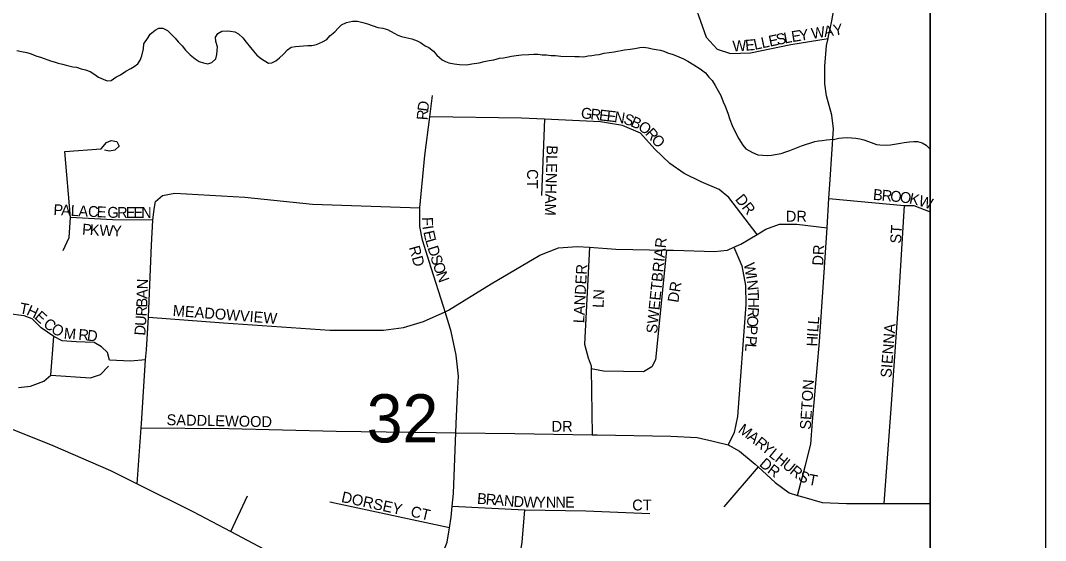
# Model space of a CAD drawing. Extents: x -209 to 4852, y 0 to 905.
# Drawn here: x 555.98 to 573.77, y 228.69 to 237.73 of the extents above; entities that cross this region are included whole.
import ezdxf

# ---------------------------------------------------------------- set-up
doc = ezdxf.new("R2010")
doc.units = 0
for name, color, linetype in [('Default', 7, 'Continuous'), ('GM_X_County_Road', 7, 'Continuous'), ('GM_X_County_Road_Text', 7, 'Continuous'), ('GM_X_Interstate_Location', 7, 'Continuous'), ('GM_X_Minor_Lake_Text', 7, 'Continuous'), ('GM_X_Minor_River', 7, 'Continuous'), ('GM_X_Township_Road_Text', 7, 'Continuous'), ('GM_X_Township_Text', 7, 'Continuous'), ('SH_Data', 7, 'Continuous')]:
    doc.layers.add(name, color=color, linetype=linetype)

msp = doc.modelspace()

# ---------------------------------------------------------------- linework, layer by layer
at = {"layer": 'Default'}
msp.add_lwpolyline([(571.768, 202.559), (571.768, 338.559), (435.768, 338.559), (435.768, 202.559)], close=True, dxfattribs=at)
at = {"layer": 'GM_X_County_Road'}
for points in [[(557.712, 236.78), (557.805, 236.846), (557.89, 236.89), (557.951, 236.926), (558.013, 236.971), (558.053, 237.038), (558.085, 237.113), (558.111, 237.234), (558.121, 237.318), (558.192, 237.43), (558.231, 237.49), (558.317, 237.556), (558.378, 237.592), (558.447, 237.591), (558.53, 237.551), (558.589, 237.496), (558.663, 237.418), (558.715, 237.356), (558.782, 237.286), (558.841, 237.208), (558.922, 237.13), (559.012, 237.06), (559.079, 237.012), (559.155, 236.988), (559.23, 236.971), (559.299, 236.999), (559.369, 237.058), (559.386, 237.134), (559.397, 237.271), (559.369, 237.362), (559.363, 237.439), (559.403, 237.499), (559.472, 237.542), (559.564, 237.548), (559.625, 237.539), (559.7, 237.529), (559.76, 237.497), (559.835, 237.427), (559.894, 237.349), (559.967, 237.256), (560.019, 237.194), (560.078, 237.124), (560.16, 237.061), (560.28, 236.982), (560.341, 236.989), (560.41, 237.025), (560.473, 237.077), (560.543, 237.143), (560.613, 237.217), (560.675, 237.262), (560.751, 237.275), (560.82, 237.281), (560.889, 237.287), (560.965, 237.292), (561.033, 237.291), (561.117, 237.311), (561.217, 237.354), (561.294, 237.398), (561.349, 237.458), (561.435, 237.532), (561.489, 237.591), (561.552, 237.65), (561.636, 237.694), (561.743, 237.714), (561.827, 237.712), (561.918, 237.694), (562.001, 237.669), (562.182, 237.604), (562.265, 237.594), (562.348, 237.57), (562.461, 237.506), (562.528, 237.474), (562.589, 237.45), (562.664, 237.432), (562.77, 237.407), (562.861, 237.374), (562.921, 237.342), (563.003, 237.287), (563.063, 237.255), (563.145, 237.192), (563.204, 237.122), (563.294, 237.044), (563.354, 237.012), (563.414, 236.988), (563.505, 236.971), (563.596, 236.961), (563.725, 236.957), (563.809, 236.971), (563.939, 236.99), (564.023, 237.011), (564.115, 237.031), (564.191, 237.045), (564.291, 237.073), (564.359, 237.079), (564.421, 237.092), (564.497, 237.106), (564.581, 237.119), (564.673, 237.132), (564.802, 237.136), (564.886, 237.141), (564.962, 237.14)], [(555.912, 237.205), (555.995, 237.188), (556.086, 237.171), (556.162, 237.146), (556.244, 237.113), (556.343, 237.081), (556.501, 237.023), (556.561, 237.007), (556.629, 236.982), (556.705, 236.965), (556.773, 236.948), (556.886, 236.923), (556.947, 236.913), (557.03, 236.889), (557.106, 236.871), (557.188, 236.839), (557.248, 236.799), (557.331, 236.744), (557.413, 236.704), (557.481, 236.68), (557.55, 236.685), (557.635, 236.744), (557.712, 236.78)], [(564.962, 237.14), (565.03, 237.13), (565.106, 237.128), (565.19, 237.119), (565.266, 237.117), (565.357, 237.107), (565.6, 237.101), (565.676, 237.099), (565.752, 237.097), (565.828, 237.11), (565.897, 237.116), (565.958, 237.13), (566.019, 237.136), (566.111, 237.157), (566.279, 237.183), (566.462, 237.216), (566.561, 237.229), (566.638, 237.242), (566.729, 237.255), (566.79, 237.261), (566.874, 237.252), (566.942, 237.235), (567.01, 237.225), (567.086, 237.208), (567.146, 237.192), (567.206, 237.167), (567.304, 237.134), (567.402, 237.094), (567.485, 237.062), (567.56, 237.022), (567.665, 236.958), (567.777, 236.887), (567.867, 236.816), (567.926, 236.739), (567.985, 236.684), (568.037, 236.599), (568.088, 236.507), (568.131, 236.422), (568.174, 236.314), (568.21, 236.238), (568.253, 236.115), (568.288, 236.007), (568.331, 235.9), (568.403, 235.746), (568.447, 235.669), (568.513, 235.561), (568.565, 235.499), (568.685, 235.435), (568.775, 235.395), (568.935, 235.383), (569.011, 235.389), (569.11, 235.402), (569.179, 235.415), (569.263, 235.443), (569.332, 235.465), (569.532, 235.551), (569.762, 235.621), (569.831, 235.635), (569.892, 235.641), (569.968, 235.654), (570.029, 235.66), (570.113, 235.666), (570.182, 235.679), (570.243, 235.685), (570.326, 235.691), (570.402, 235.689), (570.478, 235.679), (570.547, 235.67), (570.615, 235.653), (570.697, 235.621), (570.833, 235.572), (570.894, 235.563), (571.015, 235.56), (571.076, 235.566), (571.145, 235.579), (571.252, 235.592), (571.313, 235.605), (571.405, 235.618), (571.481, 235.624), (571.549, 235.622), (571.625, 235.598), (571.7, 235.558), (571.768, 235.492)]]:
    msp.add_lwpolyline(points, dxfattribs=at)
at = {"layer": 'GM_X_County_Road_Text'}
msp.add_lwpolyline([(554.875, 231.005), (556.54, 230.339), (557.539, 229.91), (558.003, 229.678), (558.966, 229.196), (559.628, 228.845), (560.489, 228.388), (562.093, 227.608), (562.726, 227.285), (563.943, 226.661), (565.196, 226.052), (565.675, 225.818), (566.474, 225.41), (567.714, 224.775), (569.815, 223.725), (570.343, 223.445), (571.432, 222.869), (571.65, 222.76), (571.768, 222.7)], dxfattribs=at)
at = {"layer": 'GM_X_Minor_Lake_Text'}
msp.add_lwpolyline([(529.706, 202.559), (571.768, 202.559), (571.768, 262.071), (562.454, 262.602), (559.929, 262.758), (554.405, 263.075), (535.693, 268.436), (531.778, 225.399), (531.472, 222.006), (531.173, 218.724), (530.557, 211.945), (530.109, 207.025), (529.915, 204.912), (529.85, 204.169)], close=True, dxfattribs=at)
at = {"layer": 'GM_X_Minor_River'}
msp.add_lwpolyline([(571.768, 220.234), (571.768, 241.24), (553.028, 241.998), (551.202, 220.877)], close=True, dxfattribs=at)
at = {"layer": 'GM_X_Township_Text'}
for points in [[(570.002, 237.453), (570.03, 237.583), (570.059, 237.718), (570.18, 238.414), (570.301, 238.989), (570.301, 239.32), (570.291, 239.477), (570.271, 239.836), (570.18, 240.472), (570.018, 241.325)], [(567.682, 237.993), (567.876, 237.438), (568.069, 237.231), (568.301, 237.154), (568.65, 237.167), (569.347, 237.309), (569.994, 237.414)], [(569.463, 229.475), (569.605, 230.002), (569.696, 230.365), (569.726, 230.758), (569.847, 232.15), (569.976, 234.123), (570.008, 234.635), (570.029, 234.964), (570.09, 235.842), (570.059, 236.084), (569.968, 236.417), (569.938, 236.628), (569.938, 236.931), (569.968, 237.294), (569.994, 237.414), (570.002, 237.453)], [(558.003, 229.678), (558.07, 230.646), (558.076, 230.722), (558.15, 231.829), (558.162, 232.001), (558.197, 232.57), (558.206, 232.716), (558.249, 233.821), (558.276, 234.259), (558.299, 234.448), (558.321, 234.579), (558.44, 234.683), (558.654, 234.724), (559.874, 234.656), (561.045, 234.536), (562.909, 234.471), (562.996, 235.381), (563.08, 236.055), (563.126, 236.421)], [(568.761, 234.01), (568.27, 234.653), (568.104, 234.788), (567.794, 234.922), (567.494, 235.067), (567.246, 235.243), (566.988, 235.491), (566.74, 235.77), (566.429, 235.904), (566.047, 235.966), (565.07, 236.011), (564.671, 236.029), (563.08, 236.055)], [(565.07, 236.011), (565.023, 234.684)], [(556.718, 233.727), (556.823, 233.955), (556.846, 234.301), (556.745, 235.448), (557.379, 235.499), (557.47, 235.608), (557.552, 235.64), (557.652, 235.626), (557.688, 235.54), (557.615, 235.476), (557.524, 235.453), (557.433, 235.476)], [(570.008, 234.635), (571.315, 234.51), (571.482, 234.51), (571.768, 234.399)], [(571.315, 234.51), (571.209, 232.801), (571.088, 231.061), (570.963, 229.336)], [(563.565, 231.236), (563.581, 231.545), (563.538, 231.913), (563.451, 232.325), (563.349, 232.667), (563.321, 232.758), (563.104, 233.43), (562.953, 233.907), (562.909, 234.146), (562.909, 234.471)], [(558.276, 234.259), (557.574, 234.264), (556.846, 234.301)], [(568.251, 233.738), (568.361, 233.787), (568.48, 233.842), (568.761, 234.01), (568.914, 234.102), (569.152, 234.188), (569.455, 234.188), (569.976, 234.123)], [(558.197, 232.57), (559.499, 232.475), (561.349, 232.347), (562.281, 232.347), (562.628, 232.39), (562.974, 232.498), (563.349, 232.667), (563.408, 232.693), (564.145, 233.148), (564.99, 233.647), (565.315, 233.777), (565.641, 233.799), (565.852, 233.785), (566.313, 233.755), (567.19, 233.736), (567.31, 233.733), (568.025, 233.712), (568.242, 233.733), (568.251, 233.738)], [(565.852, 233.785), (565.768, 232.1), (565.829, 231.862), (565.881, 231.727), (565.882, 231.673), (565.898, 230.527)], [(568.361, 233.787), (568.497, 233.464), (568.559, 233.123), (568.57, 232.792), (568.425, 230.848), (568.363, 230.569), (568.263, 230.352)], [(567.19, 233.736), (566.998, 231.831), (566.936, 231.707), (566.791, 231.624), (566.098, 231.635), (565.882, 231.673)], [(558.15, 231.829), (557.886, 231.807), (557.52, 231.823), (557.488, 231.96), (557.383, 232.056), (557.259, 232.131), (556.943, 232.142), (556.702, 232.159), (556.557, 232.235), (556.336, 232.386), (556.179, 232.54), (556.042, 232.593), (555.77, 232.627)], [(556.506, 231.566), (556.557, 232.235)], [(555.941, 231.35), (556.154, 231.373), (556.38, 231.459), (556.506, 231.566), (557.195, 231.518), (557.368, 231.578), (557.506, 231.719)], [(562.726, 227.285), (562.996, 227.86), (563.278, 228.402), (563.386, 228.663), (563.424, 228.912), (563.451, 229.096), (563.472, 229.288), (563.495, 229.508), (563.517, 230.115), (563.533, 230.564), (563.538, 230.721), (563.565, 231.231), (563.565, 231.236)], [(558.07, 230.646), (559.593, 230.635), (561.457, 230.592), (563.191, 230.57), (563.533, 230.564), (564.557, 230.548), (565.898, 230.527), (565.987, 230.526), (567.266, 230.504), (567.721, 230.482), (568.003, 230.418), (568.263, 230.352)], [(568.263, 230.352), (568.455, 230.244), (568.727, 230.017), (568.779, 229.97), (569.075, 229.699), (569.318, 229.518), (569.463, 229.475), (569.575, 229.442), (569.893, 229.351), (570.316, 229.336), (570.963, 229.336), (571.768, 229.336)], [(568.779, 229.97), (568.183, 229.276)], [(559.628, 228.845), (559.918, 229.465)], [(563.424, 228.912), (561.349, 229.356)], [(563.472, 229.288), (564.73, 229.226), (565.792, 229.204), (566.898, 229.161)], [(563.943, 226.661), (564.275, 227.297), (564.513, 227.904), (564.622, 228.272), (564.687, 228.662), (564.73, 229.226)]]:
    msp.add_lwpolyline(points, dxfattribs=at)
at = {"layer": 'SH_Data'}
for p, q in [((573.768, 340.559), (573.768, 200.559)), ((571.768, 338.559), (571.768, 202.559))]:
    msp.add_line(p, q, dxfattribs=at)

# ---------------------------------------------------------------- texts
at = {"layer": 'GM_X_Interstate_Location'}
for s, height, rotation, p in [('S', 0.189, 12.0622, (569.114, 237.298)), ('L', 0.189, 10.9402, (569.243, 237.325)), ('E', 0.189, 9.1928, (569.373, 237.35)), ('Y', 0.189, 8.8226, (569.504, 237.371)), ('W', 0.189, 8.8234, (569.718, 237.405)), ('A', 0.189, 8.8226, (569.933, 237.438)), ('Y', 0.189, 8.8226, (570.097, 237.463)), ('W', 0.189, 2.9774, (568.341, 237.188)), ('E', 0.189, 4.5939, (568.563, 237.2)), ('L', 0.189, 11.9986, (568.723, 237.214)), ('L', 0.189, 12.0622, (568.853, 237.242)), ('E', 0.189, 12.0547, (568.984, 237.27)), ('D', 0.189, 82.7231, (563.053, 236.137)), ('R', 0.189, 85.7223, (563.042, 235.99)), ('G', 0.189, 353.4064, (565.697, 236.03)), ('R', 0.189, 353.3809, (565.862, 236.01)), ('E', 0.189, 353.4219, (566.012, 235.993)), ('E', 0.189, 353.4003, (566.144, 235.978)), ('N', 0.189, 351.1774, (566.275, 235.963)), ('S', 0.189, 340.4766, (566.43, 235.94)), ('B', 0.189, 336.7281, (566.553, 235.896)), ('O', 0.189, 325.2247, (566.682, 235.842)), ('R', 0.189, 312.2002, (566.81, 235.754)), ('O', 0.189, 312.8974, (566.913, 235.641)), ('BLENHAM', 0.1894, 268.3406, (565.113, 235.56)), ('CT', 0.1894, 270, (564.771, 235.144)), ('DR', 0.1894, 308.6634, (568.372, 234.616)), ('B', 0.189, 354.6883, (570.768, 234.612)), ('R', 0.189, 354.6883, (570.918, 234.599)), ('O', 0.189, 354.6883, (571.067, 234.585)), ('O', 0.189, 352.3472, (571.231, 234.57)), ('K', 0.189, 347.6649, (571.392, 234.548)), ('W', 0.189, 342.9827, (571.551, 234.513)), ('P', 0.189, 357.2399, (556.546, 234.346)), ('A', 0.189, 357.2446, (556.679, 234.34)), ('L', 0.189, 357.2399, (556.846, 234.332)), ('A', 0.189, 357.2446, (556.979, 234.325)), ('C', 0.189, 357.2482, (557.146, 234.317)), ('E', 0.189, 357.2399, (557.295, 234.31)), ('G', 0.189, 358.394, (557.483, 234.301)), ('R', 0.189, 359.9466, (557.655, 234.296)), ('E', 0.189, 359.9956, (557.805, 234.296)), ('E', 0.189, 359.9956, (557.938, 234.296)), ('N', 0.189, 359.9929, (558.072, 234.296)), ('DR', 0.1894, 0, (569.261, 234.23)), ('P', 0.189, 356.2822, (557.043, 234.008)), ('K', 0.189, 356.4071, (557.176, 233.999)), ('W', 0.189, 357.0462, (557.345, 233.989)), ('Y', 0.189, 358.9102, (557.568, 233.977)), ('F', 0.189, 271.5031, (562.947, 234.309)), ('I', 0.189, 278.9586, (562.953, 234.149)), ('ST', 0.1894, 86.4254, (571.259, 233.846)), ('E', 0.189, 282.5544, (562.968, 234.054)), ('RD', 0.1894, 285.526, (562.718, 233.784)), ('L', 0.189, 286.4934, (563.001, 233.91)), ('D', 0.189, 287.1881, (563.039, 233.78)), ('SWEETBRIAR', 0.1894, 84.224, (567.026, 232.281)), ('DR', 0.1894, 86.9884, (569.909, 233.463)), ('S', 0.189, 287.3772, (563.089, 233.62)), ('O', 0.189, 289.2108, (563.131, 233.487)), ('LANDER', 0.1894, 86.9313, (565.76, 232.463)), ('W', 0.189, 280.1755, (568.53, 233.5)), ('N', 0.189, 290.2016, (563.187, 233.326)), ('I', 0.189, 280.1858, (568.568, 233.287)), ('N', 0.189, 88.2074, (558.186, 233.054)), ('DR', 0.1894, 81.0327, (567.394, 232.816)), ('N', 0.189, 276.3957, (568.582, 233.208)), ('B', 0.189, 87.9147, (558.176, 232.736)), ('A', 0.189, 88.2251, (558.181, 232.887)), ('LN', 0.1894, 86.9775, (566.097, 232.729)), ('T', 0.189, 272.9252, (568.6, 233.046)), ('H', 0.189, 270.5246, (568.607, 232.915)), ('T', 0.189, 349.1454, (555.949, 232.641)), ('H', 0.189, 335.4095, (556.068, 232.62)), ('R', 0.189, 86.4633, (558.166, 232.581)), ('MEADOWVIEW', 0.1894, 355.4707, (558.615, 232.596)), ('R', 0.189, 266.2812, (568.609, 232.752)), ('E', 0.189, 317.7061, (556.207, 232.559)), ('C', 0.189, 322.9625, (556.358, 232.421)), ('U', 0.189, 85.9315, (558.154, 232.413)), ('O', 0.189, 265.6901, (568.599, 232.603)), ('L', 0.189, 85.3498, (569.833, 232.439)), ('O', 0.189, 327.5966, (556.492, 232.321)), ('M', 0.189, 354.7134, (556.724, 232.201)), ('R', 0.189, 355.7466, (556.977, 232.178)), ('D', 0.189, 352.791, (557.124, 232.167)), ('D', 0.189, 85.9533, (558.142, 232.247)), ('P', 0.189, 265.6788, (568.587, 232.437)), ('L', 0.189, 85.377, (569.822, 232.306)), ('SIENNA', 0.1894, 85.5135, (571.092, 231.513)), ('P', 0.189, 265.6853, (568.573, 232.254)), ('H', 0.189, 87.5513, (569.809, 232.059)), ('I', 0.189, 85.7991, (569.816, 232.224)), ('L', 0.189, 265.6958, (568.563, 232.121)), ('SETON', 0.1894, 86.183, (569.692, 230.613)), ('SADDLEWOOD', 0.1894, 358.8315, (558.512, 230.696)), ('DR', 0.1894, 0, (565.195, 230.58)), ('M', 0.189, 323.4798, (568.419, 230.583)), ('A', 0.189, 322.0503, (568.578, 230.465)), ('R', 0.189, 320.7978, (568.709, 230.363)), ('Y', 0.189, 320.7906, (568.825, 230.268)), ('L', 0.189, 320.7874, (568.954, 230.163)), ('H', 0.189, 320.7906, (569.058, 230.079)), ('D', 0.189, 319.0218, (568.788, 230)), ('U', 0.189, 320.7833, (569.187, 229.973)), ('R', 0.189, 323.7474, (568.927, 229.88)), ('R', 0.189, 320.819, (569.316, 229.868)), ('S', 0.189, 330.1027, (569.46, 229.754)), ('T', 0.189, 349.3199, (569.64, 229.664)), ('DORSEY', 0.1894, 347.691, (561.535, 229.362)), ('B', 0.189, 355.4542, (563.897, 229.33)), ('R', 0.189, 355.4617, (564.047, 229.318)), ('A', 0.189, 355.4549, (564.197, 229.306)), ('N', 0.189, 355.4656, (564.363, 229.293)), ('D', 0.189, 355.7815, (564.53, 229.279)), ('W', 0.189, 359.0644, (564.708, 229.267)), ('Y', 0.189, 0.0154, (564.928, 229.263)), ('N', 0.189, 0, (565.095, 229.263)), ('N', 0.189, 0, (565.261, 229.263)), ('E', 0.189, 0, (565.428, 229.263)), ('CT', 0.1894, 0, (566.595, 229.213)), ('CT', 0.1894, 346.753, (562.736, 229.112))]:
    msp.add_text(s, height=height, rotation=rotation, dxfattribs=at).set_placement(p)
at = {"layer": 'GM_X_Township_Road_Text'}
msp.add_text('32', height=0.8371, rotation=0, dxfattribs=at).set_placement((561.986, 230.395))

doc.saveas('drawing.dxf')
